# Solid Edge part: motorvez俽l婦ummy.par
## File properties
Author: morva
Template: iso metric part.par
Last saved by: morva
Revision: 6
Application: Solid Edge
Density: 4906.45254418096 kg/m^3
Accuracy: 0.990
Username: morva
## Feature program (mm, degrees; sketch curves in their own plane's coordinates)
sketch for "unnamed Protrusion 1" plane through (0, 0, 0) normal (0, 0, 1) x-axis (1, 0, 0)
  line (42, -21) -> (-42, -21)
  line (-42, -21) -> (-42, 21)
  line (-42, 21) -> (42, 21)
  line (42, 21) -> (42, -21)
  dimension (linear) = 42
  dimension (linear) = 42
extrude "unnamed Protrusion 1" add finite 149 along +normal
sketch for "ExtrudedProtrusion_2" plane through (0, 0, 149) normal (0, 0, 1) x-axis (1, 0, 0)
  line (-12, 4) -> (12, 4)
  line (12, -4) -> (-12, -4)
extrude "ExtrudedProtrusion_2" add finite 10 along +normal
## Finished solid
Body 1: solid body, 11 faces, 24 edges, 16 vertices.
  Faces by surface: plane 9, cylinder 2
  Edges by curve: line 20, circle 4
Bounding box of the edges (mm): 84.000 x 42.000 x 159.000, from (-42, -21, 0) to (42, 21, 159).
Cylindrical faces by radius (mm): R4 x2
Planar faces by outward normal: +x 1, +y 2, +z 2, -x 1, -y 2, -z 1
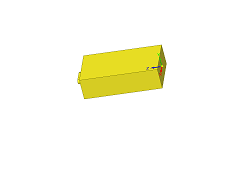
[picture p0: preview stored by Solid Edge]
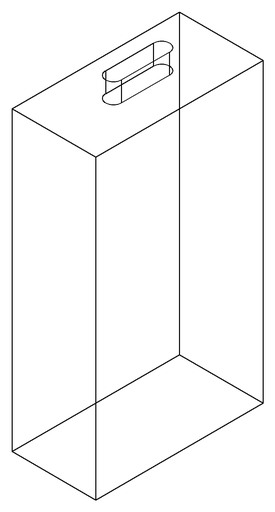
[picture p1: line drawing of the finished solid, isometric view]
